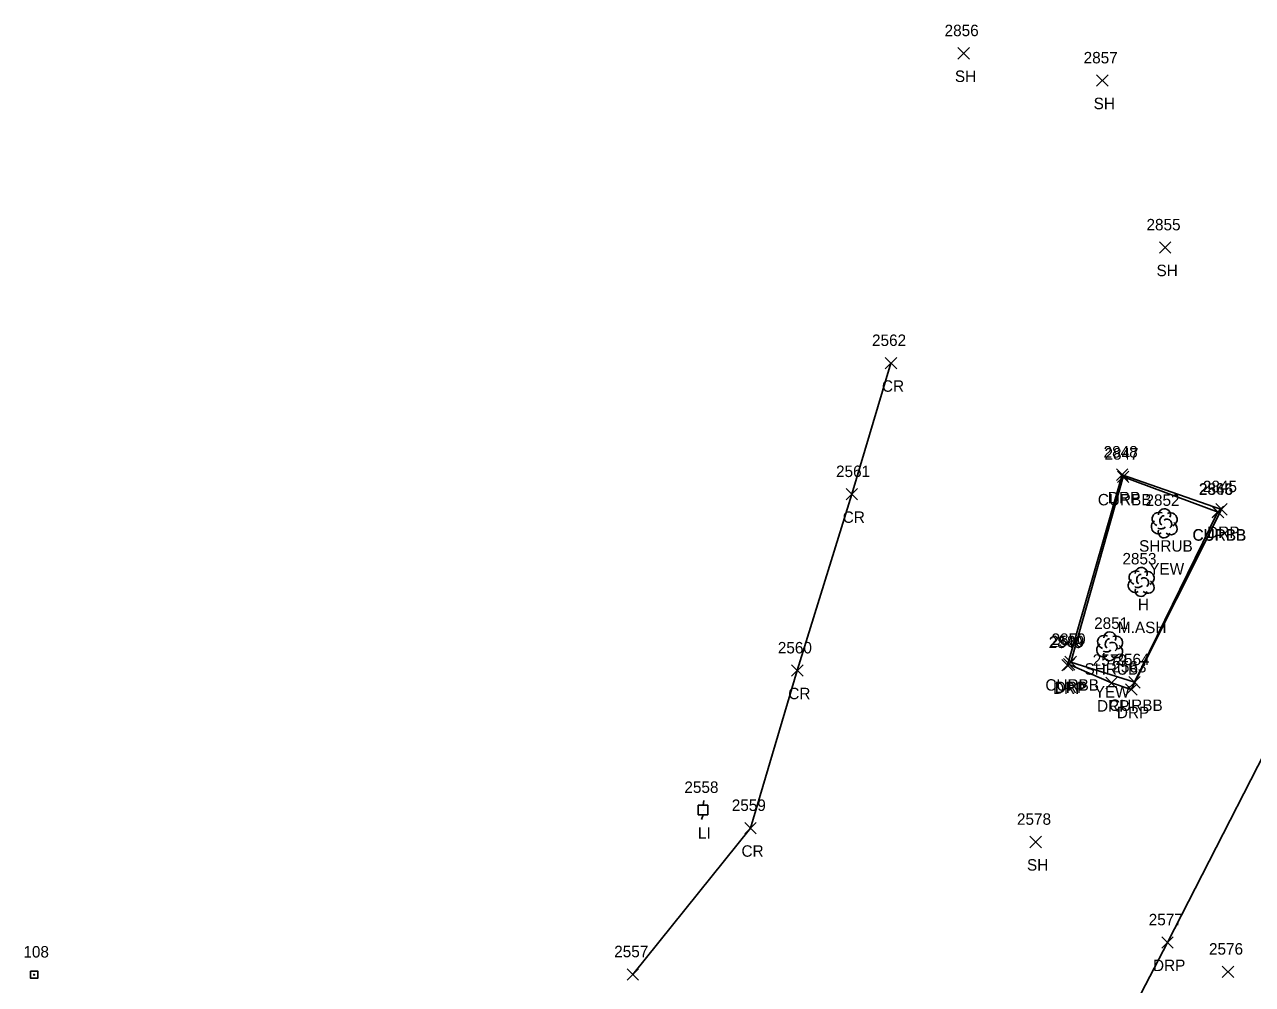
# Model space of a CAD drawing. Extents: x 1477930 to 1480780, y 774090 to 784647.
# Drawn here: x 1479188.1 to 1479402.4, y 774979 to 775146.7 of the extents above; entities that cross this region are included whole.
import ezdxf

# ---------------------------------------------------------------- set-up
doc = ezdxf.new("R2010")
doc.units = 0
for name, color, linetype in [('L_A', 7, 'Continuous'), ('L_C', 7, 'Continuous'), ('L_I', 7, 'Continuous'), ('L_TIC', 7, 'Continuous'), ('LSH', 7, 'Continuous'), ('LTD', 7, 'Continuous'), ('M_I', 7, 'Continuous'), ('MHBP', 7, 'Continuous'), ('P_A', 7, 'Continuous'), ('P_I', 7, 'Continuous'), ('P_TIC', 7, 'Continuous'), ('PRC', 7, 'Continuous'), ('R_A', 7, 'Continuous'), ('R_I', 7, 'Continuous'), ('R_TIC', 7, 'Continuous'), ('RC', 7, 'Continuous'), ('RDP', 7, 'Continuous'), ('U_A', 7, 'Continuous'), ('U_I', 7, 'Continuous'), ('ULP', 7, 'Continuous')]:
    doc.layers.add(name, color=color, linetype=linetype)

msp = doc.modelspace()

# ---------------------------------------------------------------- linework, layer by layer
at = {"layer": 'L_TIC'}
for points in [[(1479350.98, 775140.62), (1479352.98, 775142.62)], [(1479352.98, 775140.62), (1479350.98, 775142.62)], [(1479375.19, 775135.87), (1479377.19, 775137.87)], [(1479377.19, 775135.87), (1479375.19, 775137.87)], [(1479386.16, 775106.71), (1479388.16, 775108.71)], [(1479388.16, 775106.71), (1479386.16, 775108.71)], [(1479363.55, 775002.9), (1479365.55, 775004.9)], [(1479365.55, 775002.9), (1479363.55, 775004.9)], [(1479397.12, 774980.23), (1479399.12, 774982.23)], [(1479399.12, 774980.23), (1479397.12, 774982.23)]]:
    msp.add_lwpolyline(points, dxfattribs=at)
at = {"layer": 'LSH'}
for p, q in [((1479386.98, 775059.6), (1479386.98, 775059.6)), ((1479386.98, 775059.6), (1479386.98, 775059.6)), ((1479377.45, 775038.11), (1479377.45, 775038.11)), ((1479377.45, 775038.11), (1479377.45, 775038.11))]:
    msp.add_line(p, q, dxfattribs=at)
for centre in [(1479387.03, 775061.04), (1479377.5, 775039.54)]:
    msp.add_arc(centre, 1.05, 335.5272, 180.9563, dxfattribs=at)
for centre, major_axis, ratio, start_param, end_param in [((1479386.19, 775060.27), (1.21, -0.51), 0.895232, 1.570796, 4.712389), ((1479386.77, 775060.06), (-0.208, -0.792), 0.645439, 3.141593, 6.283185), ((1479387.48, 775059.44), (-0.5, 0.667), 0.989748, 3.141593, 6.283185), ((1479388.02, 775060.19), (-1.14, -0.48), 0.949671, 1.570796, 4.712389), ((1479385.9, 775058.9), (0.58, -1.04), 0.959034, 3.141593, 6.283185), ((1479386.98, 775058.1), (0.26, 1.06), 0.942809, 1.570796, 4.712389), ((1479386.52, 775058.85), (-0.625, -0.083), 0.423636, 0, 3.141593), ((1479387.98, 775058.77), (-1.09, 0.79), 0.841452, 1.570796, 4.712389), ((1479376.66, 775038.78), (1.21, -0.51), 0.895232, 1.570796, 4.712389), ((1479377.25, 775038.57), (-0.208, -0.792), 0.645439, 3.141593, 6.283185), ((1479377.95, 775037.94), (-0.5, 0.667), 0.989748, 3.141593, 6.283185), ((1479378.5, 775038.69), (-1.14, -0.48), 0.949671, 1.570796, 4.712389), ((1479376.37, 775037.4), (0.58, -1.04), 0.959034, 3.141593, 6.283185), ((1479377.45, 775036.61), (0.26, 1.06), 0.942809, 1.570796, 4.712389), ((1479377, 775037.36), (-0.625, -0.083), 0.423636, 0, 3.141593), ((1479378.45, 775037.28), (-1.09, 0.79), 0.841452, 1.570796, 4.712389)]:
    msp.add_ellipse(centre, major_axis=major_axis, ratio=ratio, start_param=start_param, end_param=end_param, dxfattribs=at)
at = {"layer": 'LTD'}
msp.add_line((1479382.96, 775049.37), (1479382.96, 775049.37), dxfattribs=at)
msp.add_line((1479382.96, 775049.37), (1479382.96, 775049.37), dxfattribs=at)
msp.add_arc((1479383, 775050.8), 1.05, 335.5272, 180.9563, dxfattribs=at)
for centre, major_axis, ratio, start_param, end_param in [((1479381.87, 775048.66), (0.58, -1.04), 0.959034, 3.141593, 6.283185), ((1479382.17, 775050.03), (1.21, -0.51), 0.895232, 1.570796, 4.712389), ((1479382.75, 775049.83), (-0.208, -0.792), 0.645439, 3.141593, 6.283185), ((1479383.46, 775049.2), (-0.5, 0.667), 0.989748, 3.141593, 6.283185), ((1479383.96, 775048.53), (-1.09, 0.79), 0.841452, 1.570796, 4.712389), ((1479384, 775049.95), (-1.14, -0.48), 0.949671, 1.570796, 4.712389), ((1479382.96, 775047.87), (0.26, 1.06), 0.942809, 1.570796, 4.712389), ((1479382.5, 775048.62), (-0.625, -0.083), 0.423636, 0, 3.141593)]:
    msp.add_ellipse(centre, major_axis=major_axis, ratio=ratio, start_param=start_param, end_param=end_param, dxfattribs=at)
at = {"layer": 'MHBP'}
msp.add_lwpolyline([(1479189.11, 774981.35), (1479190.36, 774981.35), (1479190.36, 774980.1), (1479189.11, 774980.1)], close=True, dxfattribs=at)
msp.add_circle((1479189.74, 774980.72), 0.0833, dxfattribs=at)
at = {"layer": 'P_TIC'}
for points in [[(1479338.3, 775086.52), (1479340.3, 775088.52)], [(1479340.3, 775086.52), (1479338.3, 775088.52)], [(1479331.45, 775063.63), (1479333.45, 775065.63)], [(1479333.45, 775063.63), (1479331.45, 775065.63)], [(1479321.95, 775032.83), (1479323.95, 775034.83)], [(1479323.95, 775032.83), (1479321.95, 775034.83)], [(1479313.78, 775005.32), (1479315.78, 775007.32)], [(1479315.78, 775005.32), (1479313.78, 775007.32)], [(1479293.25, 774979.77), (1479295.25, 774981.77)], [(1479295.25, 774979.77), (1479293.25, 774981.77)]]:
    msp.add_lwpolyline(points, dxfattribs=at)
at = {"layer": 'PRC'}
msp.add_lwpolyline([(1479294.25, 774980.77), (1479314.78, 775006.32), (1479322.95, 775033.83), (1479332.45, 775064.63), (1479339.3, 775087.52)], dxfattribs=at)
at = {"layer": 'R_TIC'}
for points in [[(1479378.67, 775067.04), (1479380.67, 775069.04)], [(1479380.67, 775067.04), (1479378.67, 775069.04)], [(1479378.83, 775066.68), (1479380.83, 775068.68)], [(1479380.83, 775066.68), (1479378.83, 775068.68)], [(1479395.34, 775060.55), (1479397.34, 775062.55)], [(1479397.34, 775060.55), (1479395.34, 775062.55)], [(1479395.39, 775060.5), (1479397.39, 775062.5)], [(1479397.39, 775060.5), (1479395.39, 775062.5)], [(1479396, 775060.99), (1479398, 775062.99)], [(1479398, 775060.99), (1479396, 775062.99)], [(1479369.1, 775033.76), (1479371.1, 775035.76)], [(1479371.1, 775033.76), (1479369.1, 775035.76)], [(1479369.41, 775033.92), (1479371.41, 775035.92)], [(1479371.41, 775033.92), (1479369.41, 775035.92)], [(1479369.67, 775034.32), (1479371.67, 775036.32)], [(1479371.67, 775034.32), (1479369.67, 775036.32)], [(1479369.67, 775034.32), (1479371.67, 775036.32)], [(1479371.67, 775034.32), (1479369.67, 775036.32)], [(1479376.78, 775030.67), (1479378.78, 775032.67)], [(1479378.78, 775030.67), (1479376.78, 775032.67)], [(1479380.79, 775030.78), (1479382.79, 775032.78)], [(1479382.79, 775030.78), (1479380.79, 775032.78)], [(1479380.79, 775030.78), (1479382.79, 775032.78)], [(1479382.79, 775030.78), (1479380.79, 775032.78)], [(1479380.25, 775029.51), (1479382.25, 775031.51)], [(1479382.25, 775029.51), (1479380.25, 775031.51)], [(1479380.25, 775029.51), (1479382.25, 775031.51)], [(1479382.25, 775029.51), (1479380.25, 775031.51)], [(1479386.55, 774985.35), (1479388.55, 774987.35)], [(1479388.55, 774985.35), (1479386.55, 774987.35)]]:
    msp.add_lwpolyline(points, dxfattribs=at)
at = {"layer": 'RC'}
for points in [[(1479381.79, 775031.78), (1479396.34, 775061.55), (1479396.39, 775061.5), (1479379.83, 775067.68), (1479370.67, 775035.32)], [(1479381.79, 775031.78), (1479370.67, 775035.32)]]:
    msp.add_lwpolyline(points, dxfattribs=at)
at = {"layer": 'RDP'}
for points in [[(1479381.25, 775030.51), (1479397, 775061.99), (1479379.67, 775068.04), (1479370.1, 775034.76)], [(1479341.82, 774898.99), (1479353.71, 774920.58), (1479370.62, 774953.72), (1479387.55, 774986.35), (1479411.83, 775033.72), (1479422.89, 775054.64)], [(1479381.25, 775030.51), (1479377.78, 775031.67), (1479370.41, 775034.92)]]:
    msp.add_lwpolyline(points, dxfattribs=at)
at = {"layer": 'ULP'}
for p, q in [((1479306.66, 775011.14), (1479306.5, 775010.31)), ((1479305.66, 775008.64), (1479305.66, 775010.31)), ((1479305.66, 775010.31), (1479307.33, 775010.31)), ((1479307.33, 775008.64), (1479305.66, 775008.64)), ((1479306.25, 775007.81), (1479306.5, 775008.64)), ((1479306.5, 775009.47), (1479306.5, 775009.47)), ((1479307.33, 775010.31), (1479307.33, 775008.64))]:
    msp.add_line(p, q, dxfattribs=at)

# ---------------------------------------------------------------- texts
at = {"layer": 'L_A'}
for s, p in [('SH', (1479350.46, 775136.62)), ('SH', (1479374.67, 775131.87)), ('SH', (1479385.65, 775102.71)), ('SHRUB', (1479382.61, 775054.6)), ('H', (1479382.39, 775044.37)), ('SHRUB', (1479373.08, 775033.11)), ('SH', (1479363.04, 774998.9))]:
    msp.add_text(s, height=2, dxfattribs=at).set_placement(p)
at = {"layer": 'L_C'}
for s, p in [('YEW', (1479384.38, 775050.6)), ('M.ASH', (1479378.91, 775040.37)), ('YEW', (1479374.86, 775029.11))]:
    msp.add_text(s, height=2, dxfattribs=at).set_placement(p)
at = {"layer": 'L_I'}
for s, p in [('2856', (1479348.66, 775144.62)), ('2857', (1479372.93, 775139.87)), ('2855', (1479383.9, 775110.71)), ('2852', (1479383.72, 775062.6)), ('2853', (1479379.7, 775052.37)), ('2851', (1479374.76, 775041.11)), ('2578', (1479361.29, 775006.9)), ('2576', (1479394.81, 774984.23))]:
    msp.add_text(s, height=2, dxfattribs=at).set_placement(p)
at = {"layer": 'M_I'}
msp.add_text('108', height=2, dxfattribs=at).set_placement((1479187.86, 774983.72))
at = {"layer": 'P_A'}
for p in [(1479337.73, 775082.52), (1479330.88, 775059.63), (1479321.38, 775028.83), (1479313.21, 775001.32)]:
    msp.add_text('CR', height=2, dxfattribs=at).set_placement(p)
at = {"layer": 'P_I'}
for s, p in [('2562', (1479335.99, 775090.52)), ('2561', (1479329.71, 775067.63)), ('2560', (1479319.55, 775036.83)), ('2559', (1479311.51, 775009.32)), ('2557', (1479290.99, 774983.77))]:
    msp.add_text(s, height=2, dxfattribs=at).set_placement(p)
at = {"layer": 'R_A'}
for s, p in [('CURBB', (1479375.41, 775062.68)), ('DRP', (1479377.16, 775063.04)), ('CURBB', (1479391.92, 775056.55)), ('CURBB', (1479391.97, 775056.5)), ('DRP', (1479394.49, 775056.99)), ('CURBB', (1479366.25, 775030.32)), ('CURBB', (1479366.25, 775030.32)), ('DRP', (1479367.59, 775029.76)), ('DRP', (1479367.9, 775029.92)), ('DRP', (1479375.27, 775026.67)), ('CURBB', (1479377.37, 775026.78)), ('CURBB', (1479377.37, 775026.78)), ('DRP', (1479378.73, 775025.51)), ('DRP', (1479378.73, 775025.51)), ('DRP', (1479385.04, 774981.35))]:
    msp.add_text(s, height=2, dxfattribs=at).set_placement(p)
at = {"layer": 'R_I'}
for s, p in [('2848', (1479376.41, 775071.04)), ('2847', (1479376.57, 775070.68)), ('2565', (1479393.03, 775064.55)), ('2846', (1479393.07, 775064.5)), ('2845', (1479393.74, 775064.99)), ('2849', (1479366.83, 775037.76)), ('2580', (1479367.06, 775037.92)), ('2850', (1479367.32, 775038.32)), ('2850', (1479367.32, 775038.32)), ('2579', (1479374.51, 775034.67)), ('2564', (1479378.48, 775034.78)), ('2564', (1479378.48, 775034.78)), ('2563', (1479377.94, 775033.51)), ('2563', (1479377.94, 775033.51)), ('2577', (1479384.29, 774989.35))]:
    msp.add_text(s, height=2, dxfattribs=at).set_placement(p)
at = {"layer": 'U_A'}
msp.add_text('LI', height=2, dxfattribs=at).set_placement((1479305.6, 775004.47))
at = {"layer": 'U_I'}
msp.add_text('2558', height=2, dxfattribs=at).set_placement((1479303.24, 775012.47))

doc.saveas('drawing.dxf')
